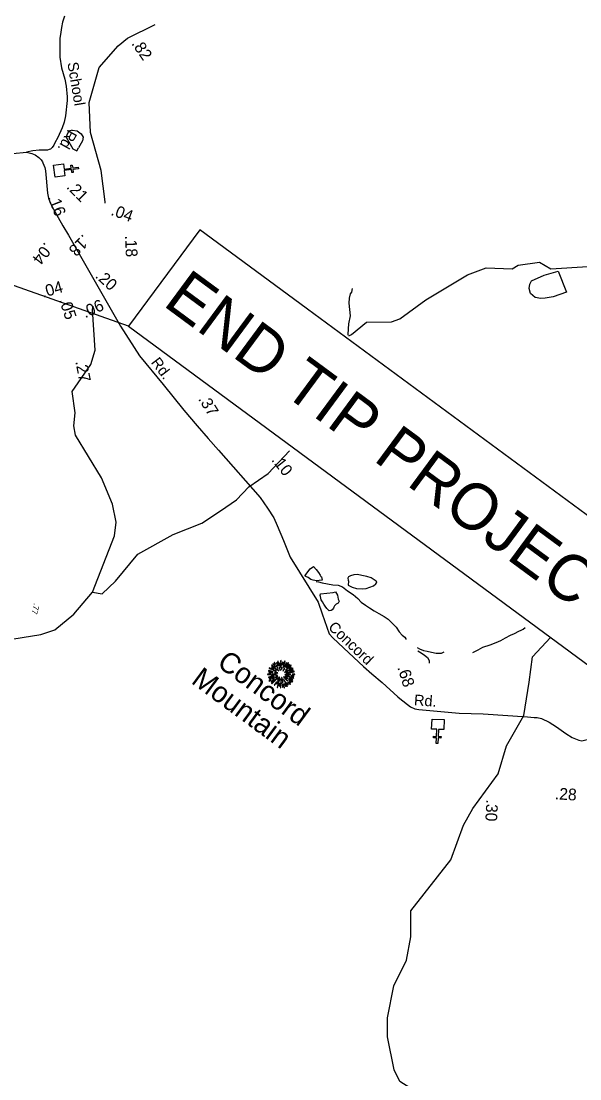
# Model space of a CAD drawing. Extents: x 945666 to 965748, y 644452 to 663300.
# Drawn here: x 954782 to 955557, y 657119 to 658587 of the extents above; entities that cross this region are included whole.
import ezdxf

# ---------------------------------------------------------------- set-up
doc = ezdxf.new("R2010")
doc.units = 0
for name, color, linetype in [('Exist Cultural Church CELL', 7, 'Continuous'), ('Exist Geographical Mountain Summit CELL', 7, 'Continuous'), ('Exist Geographical Mountain Summit Label', 7, 'Continuous'), ('Exist Hydrographic Creek Single Shore', 7, 'Continuous'), ('Exist Hydrographic Misc Water Feature', 7, 'Continuous'), ('Exist Hydrographic Pond Under 1500 Sq Ft', 7, 'Continuous'), ('Exist Road Secondary Mileage Tenths English Label', 7, 'Continuous'), ('Exist Road Secondary Type 51 Attributed', 7, 'Continuous'), ('Exist Road Secondary Type 51 Label', 7, 'Continuous'), ('Old_Level_48', 7, 'Continuous'), ('Prop EOT', 7, 'Continuous'), ('Sheet Title CELL', 7, 'Continuous')]:
    doc.layers.add(name, color=color, linetype=linetype)

msp = doc.modelspace()

# ---------------------------------------------------------------- linework, layer by layer
at = {"layer": 'Exist Cultural Church CELL'}
for points in [[(954840.6, 658388.7), (954841.5, 658381.4), (954851.3, 658382.6), (954850.8, 658386.8), (954852.8, 658387), (954853.4, 658382.9), (954861.1, 658383.9), (954861.4, 658381.8), (954853.6, 658380.8), (954854.1, 658376.7), (954852.1, 658376.5), (954851.6, 658380.6), (954841.8, 658379.3), (954842.7, 658371.9), (954828.9, 658370.2), (954826.8, 658387)], [(955368.1, 657603.7), (955360.7, 657604.1), (955360.2, 657594.2), (955364.3, 657594), (955364.2, 657591.9), (955360.1, 657592.2), (955359.7, 657584.4), (955357.6, 657584.5), (955358, 657592.3), (955353.8, 657592.5), (955354, 657594.5), (955358.1, 657594.3), (955358.6, 657604.2), (955351.1, 657604.6), (955351.8, 657618.4), (955368.8, 657617.6)]]:
    msp.add_lwpolyline(points, close=True, dxfattribs=at)
at = {"layer": 'Exist Geographical Mountain Summit CELL'}
for points in [[(955141.6, 657699.3), (955142.5, 657692.6), (955143, 657692.6), (955142.4, 657699.5)], [(955125, 657685.6), (955125, 657685), (955131.2, 657683.5), (955131.4, 657684.2)], [(955126.1, 657689.3), (955125.9, 657688.6), (955130.5, 657687), (955130.5, 657687.5)], [(955129.1, 657690.4), (955132.3, 657688.2), (955132.6, 657688.6), (955129.4, 657691)], [(955129.2, 657693.1), (955136.2, 657686.9), (955136.5, 657687.1), (955129.6, 657693.7)], [(955131.1, 657695.1), (955134.7, 657691), (955135.1, 657691.2), (955131.6, 657695.5)], [(955131.8, 657686.9), (955131.6, 657686.4), (955135.7, 657684.7), (955135.9, 657685.1)], [(955132.9, 657696.9), (955134.6, 657694.3), (955134.9, 657694.5), (955133.4, 657697.3)], [(955135.6, 657692.2), (955137.9, 657688.6), (955138.2, 657688.7), (955136.1, 657692.4)], [(955136, 657696.4), (955137.4, 657692.7), (955137.9, 657692.8), (955136.6, 657696.6)], [(955137.6, 657698.3), (955139.4, 657692), (955139.8, 657692.1), (955138.3, 657698.5)], [(955137.6, 657686.8), (955139.2, 657685.2), (955139.4, 657685.4), (955138, 657687.2)], [(955139.8, 657689.9), (955141, 657686), (955141.4, 657686.2), (955140.3, 657690.1)], [(955140.3, 657695.8), (955141.5, 657690.2), (955141.9, 657690.3), (955141, 657696.1)], [(955142.9, 657689.8), (955143.1, 657687), (955143.5, 657687.1), (955143.5, 657689.8)], [(955144.6, 657697.3), (955144.6, 657693.8), (955144.9, 657693.8), (955145.3, 657697.4)], [(955147.4, 657698.8), (955145, 657689.7), (955145.4, 657689.6), (955148.2, 657698.6)], [(955147.1, 657688.7), (955145, 657685.5), (955145.3, 657685.4), (955147.6, 657688.4)], [(955147, 657690.7), (955147.3, 657690.6), (955150, 657696.3), (955149.5, 657696.5)], [(955147.4, 657683.5), (955147.6, 657683), (955159.2, 657688.1), (955158.9, 657688.9)], [(955148.8, 657686), (955156.3, 657692.9), (955155.8, 657693.5), (955148.5, 657686.3)], [(955152.2, 657696.8), (955148.6, 657691), (955149, 657690.8), (955152.9, 657696.4)], [(955149.7, 657689.9), (955150.1, 657689.6), (955154.1, 657694.2), (955153.6, 657694.6)], [(955149.7, 657682), (955149.8, 657681.6), (955160.6, 657684), (955160.5, 657684.8)], [(955153.3, 657688.3), (955153.6, 657687.9), (955156.7, 657690), (955156.3, 657690.6)], [(955159.2, 657686.6), (955154.4, 657684.7), (955154.6, 657684.4), (955159.4, 657685.9)], [(955123.4, 657680.9), (955123.4, 657680.3), (955128, 657680.3), (955128, 657680.9)], [(955125.1, 657676.5), (955125.2, 657676), (955133.1, 657677.9), (955133, 657678.3)], [(955125.6, 657682.6), (955130, 657682.1), (955130, 657682.7), (955125.8, 657683.3)], [(955125.6, 657671.7), (955125.9, 657671.1), (955128.9, 657672.8), (955128.8, 657673.3)], [(955131.7, 657676.7), (955126.1, 657674.5), (955126.2, 657674), (955131.9, 657676.2)], [(955128.9, 657669.6), (955133.4, 657673.2), (955133.1, 657673.5), (955128.5, 657670.1)], [(955129.1, 657678.6), (955132.5, 657679), (955132.4, 657679.5), (955128.9, 657679.3)], [(955129.1, 657667.8), (955129.5, 657667.3), (955137.7, 657675.7), (955137.5, 657676)], [(955130.2, 657680.8), (955130.2, 657680.2), (955136, 657680.5), (955136, 657680.9)], [(955130.4, 657674.2), (955130.7, 657673.7), (955138, 657677.7), (955137.8, 657678)], [(955133.6, 657683.3), (955133.5, 657682.7), (955137.6, 657682), (955137.8, 657682.5)], [(955134.9, 657678.8), (955135, 657678.3), (955137.4, 657679.2), (955137.3, 657679.5)], [(955136.7, 657666.8), (955138.4, 657670.4), (955138.1, 657670.6), (955136.2, 657667.1)], [(955139.8, 657676.7), (955137.4, 657672.5), (955137.8, 657672.2), (955140.2, 657676.5)], [(955140.8, 657674.6), (955139.4, 657670.8), (955140, 657670.6), (955141.1, 657674.5)], [(955142.1, 657673.2), (955141.7, 657661.5), (955142.3, 657661.5), (955142.5, 657673.1)], [(955143.2, 657676), (955144.5, 657669.4), (955145.1, 657669.6), (955143.6, 657676.1)], [(955145.7, 657677), (955151.2, 657671), (955151.6, 657671.4), (955146.1, 657677.3)], [(955145.7, 657673.8), (955150.9, 657663.8), (955151.5, 657664.3), (955146, 657674)], [(955147.9, 657680.1), (955147.8, 657679.7), (955155.7, 657679.7), (955155.7, 657680.5)], [(955148.3, 657677.3), (955148.1, 657677), (955151.2, 657674.7), (955151.7, 657675.1)], [(955149.4, 657678.5), (955149.4, 657678.2), (955159.7, 657675.2), (955159.9, 657675.8)], [(955152.8, 657673.8), (955158.5, 657670.1), (955158.9, 657670.6), (955153, 657674.1)], [(955153.4, 657671.4), (955156, 657669.2), (955156.3, 657669.6), (955153.7, 657671.7)], [(955154.2, 657675), (955158.5, 657672.8), (955158.8, 657673.5), (955154.2, 657675.3)], [(955156.2, 657678.1), (955160.2, 657677.5), (955160.3, 657678.2), (955156.2, 657678.4)], [(955157.9, 657680.5), (955157.9, 657680), (955161.6, 657680), (955161.5, 657680.7)], [(955135.9, 657670.1), (955133, 657665.4), (955133.5, 657665.2), (955136.4, 657669.8)], [(955138.8, 657668.7), (955136.8, 657662.2), (955137.4, 657662), (955139.2, 657668.6)], [(955140.4, 657668.5), (955139.8, 657664.2), (955140.4, 657664.1), (955140.9, 657668.4)], [(955143.5, 657668), (955144.4, 657662.6), (955145, 657662.7), (955144, 657668.1)], [(955145.3, 657666.8), (955146.5, 657661.7), (955147.2, 657661.9), (955145.7, 657666.9)], [(955147.1, 657667.2), (955148.7, 657663.9), (955149.3, 657664.1), (955147.7, 657667.5)], [(955150.5, 657668.7), (955152.1, 657666.2), (955152.6, 657666.5), (955150.9, 657668.9)], [(955152.5, 657669.3), (955154.9, 657666.4), (955155.4, 657666.9), (955152.9, 657669.7)]]:
    msp.add_lwpolyline(points, close=True, dxfattribs=at)
at = {"layer": 'Exist Hydrographic Creek Single Shore'}
for points in [[(954898.3, 658334), (954898.4, 658335.9), (954892.8, 658379.4), (954878, 658432.2), (954876.4, 658473.7), (954890.1, 658522.4), (954916.7, 658552.5), (954929.3, 658563.2), (954967.7, 658582)], [(955236.5, 658150), (955240.3, 658152), (955260.7, 658169.1), (955295.4, 658169.3), (955307.2, 658173.7), (955343.4, 658200.2), (955401.2, 658234.8), (955426.9, 658244.6), (955462.8, 658242.8), (955471.2, 658248.2), (955500.7, 658252.3), (955516.6, 658242.8), (955567.8, 658246.4), (955621.9, 658264), (955644.2, 658272.6), (955662.4, 658287.1)], [(954881, 657794.4), (954911.3, 657872.7), (954913.9, 657891.7), (954908.5, 657916.3), (954893.4, 657953.1), (954857.3, 658012.1), (954855.1, 658025), (954856.9, 658043), (954852.7, 658072.6), (954878.5, 658110.3), (954884.7, 658130.3), (954881.1, 658186.8), (954881.9, 658191.2)], [(955058.3, 657907.4), (955080.6, 657922.6), (955097.7, 657940.7), (955124.7, 657959.1), (955154, 657990.5)], [(954881, 657794.4), (954894.4, 657792.1), (954912.6, 657809.9), (954943.6, 657847.3), (954992.8, 657874.5), (955032.7, 657890.1), (955058.3, 657907.4)], [(954720.4, 657112.4), (954738.9, 657151.4), (954750.2, 657247.6), (954746.3, 657261.9), (954711.5, 657308.6), (954704.7, 657355.7), (954697.4, 657378), (954701.8, 657394), (954699, 657409.6), (954705.5, 657421.2), (954706, 657435.9), (954732.3, 657481.3), (954749.4, 657520.3), (954748.5, 657529.6), (954755.3, 657569.5), (954762.6, 657645.1), (954757.2, 657699.2), (954750.3, 657720.1), (954757.3, 657727.2), (954809.4, 657735.5), (954828.6, 657742.2), (954855.2, 657763.7), (954881, 657794.4)], [(955403.4, 657010.4), (955376.7, 657048.1), (955349.4, 657065.9), (955341.2, 657076.5), (955334.8, 657098.1), (955307.2, 657115.6), (955299.4, 657131.8), (955290.1, 657177.7), (955290.2, 657203.9), (955299, 657248.2), (955316.3, 657283.9), (955322.5, 657316.2), (955322.2, 657352.4), (955378.1, 657422.9), (955395.6, 657471.2), (955408.4, 657494.3), (955443.7, 657542.3), (955455.3, 657581.3), (955478.9, 657623.4), (955486.5, 657669.6), (955491, 657704.9), (955516.3, 657731.7)]]:
    msp.add_lwpolyline(points, dxfattribs=at)
at = {"layer": 'Exist Hydrographic Misc Water Feature'}
for points in [[(955240.8, 658215.7), (955239.9, 658210.5), (955238.3, 658208.4), (955236.8, 658202.3), (955236.3, 658195.4), (955238.3, 658177.9), (955235.9, 658166.5), (955235.2, 658152.2), (955235.2, 658150.9)], [(955191.2, 657809.4), (955194.2, 657808.6), (955199.3, 657807.5), (955206.9, 657805.9), (955214.3, 657804.7), (955221.4, 657804.1), (955227.6, 657801.9), (955234.6, 657796.4), (955242.2, 657791.4), (955248.9, 657785.6), (955253.7, 657780.8), (955259.6, 657776.5), (955265.2, 657772.7), (955271.7, 657768.7), (955278.2, 657764.8), (955285.2, 657760.7), (955291.1, 657756.8), (955296.7, 657751.3), (955302.2, 657745.7), (955306, 657739.5), (955310.4, 657734.7), (955313.9, 657731.9), (955315.6, 657729.9), (955315.6, 657728.6)], [(955408.2, 657710.9), (955416, 657714.5), (955422.4, 657718), (955432.2, 657721.6), (955440.7, 657724.5), (955447.4, 657727.5), (955453.7, 657730.9), (955460.7, 657734.7), (955466.3, 657736.9), (955472.2, 657740.2), (955475.6, 657741.9), (955478, 657742.9), (955480.9, 657745.3)], [(955331.3, 657717.6), (955334.4, 657715.9), (955339.8, 657713.6), (955345, 657712.5), (955350.9, 657711.2), (955357.4, 657709.8), (955361.4, 657709.9), (955365.1, 657710), (955368.7, 657711.5)], [(955332.1, 657713), (955336.5, 657710.2), (955341.4, 657707.1), (955345.3, 657704), (955347.3, 657700.8), (955347.9, 657699), (955347.7, 657695.8)]]:
    msp.add_lwpolyline(points, dxfattribs=at)
at = {"layer": 'Exist Hydrographic Pond Under 1500 Sq Ft'}
msp.add_line((955197.7, 657816), (955198.4, 657815.6), dxfattribs=at)
for points in [[(954852.5, 658435.5), (954848, 658434.1), (954845.6, 658429.8), (954844.2, 658425.5), (954853.7, 658409.4), (954859, 658406.9), (954861.3, 658410.7)], [(954852.5, 658435.5), (954859.5, 658434.3), (954865.1, 658430.5), (954867.9, 658425.7), (954867.2, 658420.6), (954861.3, 658410.7)], [(955507.3, 658234), (955526.6, 658239.6), (955538.5, 658210.6), (955520, 658204), (955508.9, 658202.2), (955502.7, 658201.8), (955495, 658203), (955488.4, 658208.9), (955486.5, 658215.7), (955487.3, 658221.7), (955489.7, 658226.4), (955507.3, 658234)], [(955199.2, 657811), (955195.4, 657810.7), (955191.7, 657810.3), (955187.1, 657811.2), (955183.9, 657812.1), (955180, 657814.8), (955176.7, 657816.1), (955175.5, 657817), (955182.7, 657826.6)], [(955182.7, 657826.6), (955187.3, 657830), (955191, 657825.8), (955194.2, 657821.9), (955196.7, 657817.9), (955197.7, 657816)], [(955275.3, 657808.9), (955272.9, 657810.5), (955267.3, 657814.3), (955261.3, 657816.3), (955254.5, 657817.4), (955248.4, 657818.8), (955243.2, 657818.6), (955238.9, 657816.9), (955236.1, 657815.9), (955234.9, 657813.9), (955235.6, 657811), (955235.8, 657809.5)], [(955198.4, 657815.6), (955199, 657813.2), (955199.2, 657811)], [(955235.8, 657809.5), (955235.3, 657804.3), (955241, 657801.4), (955247.2, 657799.6), (955255.2, 657798.9), (955260.5, 657799.7), (955265.7, 657801.3), (955270.5, 657803.2), (955273.9, 657805.8), (955275, 657807.2), (955275.3, 657808.9)], [(955214.8, 657793.8), (955217.8, 657795.1), (955220.5, 657790.1), (955221.7, 657784.8), (955222.9, 657781.8), (955221.4, 657779.4), (955219, 657777.6), (955216.7, 657775.5), (955215.4, 657773.5), (955215, 657772.2), (955213.4, 657770.1), (955211.7, 657768.8), (955209.1, 657768.5), (955206, 657771.6), (955203.6, 657774.8), (955201.7, 657778), (955199.7, 657780.9), (955198, 657783.8), (955196.9, 657788.3), (955196.6, 657789.6), (955196.9, 657792), (955214.8, 657793.8)]]:
    msp.add_lwpolyline(points, dxfattribs=at)
at = {"layer": 'Exist Road Secondary Type 51 Attributed'}
for points in [[(954842.2, 658593.4), (954839.4, 658585.1), (954837.9, 658578), (954836.5, 658568.2), (954835.8, 658563.2), (954835.5, 658550.9), (954835.8, 658536.7), (954837.9, 658521.7), (954842.6, 658506.3), (954844.2, 658496.4), (954845.7, 658481.8), (954845.8, 658476.5), (954843.6, 658455.2), (954841.7, 658446.4), (954838.6, 658438.8), (954832.8, 658425.4), (954828.7, 658417.6), (954827.1, 658414.6), (954824.9, 658411.2), (954822.7, 658409.2), (954820.7, 658408.4), (954818.3, 658407.7), (954806.9, 658407.7), (954798.2, 658406.8), (954789.3, 658404.9)], [(954750.3, 658407.1), (954756.9, 658404.5), (954763.1, 658403.6), (954770.4, 658403.1), (954789.3, 658404.9)], [(954789.3, 658404.9), (954796.9, 658403.1), (954801.3, 658401.1), (954806.4, 658397.4), (954809.5, 658394), (954811.4, 658391.5), (954812, 658389.9), (954814.8, 658383.5), (954815.5, 658378.8), (954818.4, 658348.1), (954819.8, 658341.2), (954821.8, 658335.8), (954824.4, 658329.8), (954839.6, 658302.6), (954847.6, 658289.6)], [(954847.6, 658289.6), (954919.7, 658163.3)], [(954919.7, 658163.3), (954946.1, 658122.4), (954978.7, 658082.6)], [(954978.7, 658082.6), (955007.6, 658046.9), (955026.2, 658025)], [(955026.2, 658025), (955041.5, 658007.7), (955055.8, 657991.4), (955113.5, 657925.9), (955123.6, 657910.9), (955132.3, 657897.7), (955136.8, 657886.7), (955146, 657866), (955154.9, 657843), (955193.7, 657780.7), (955199.6, 657764.2), (955208.9, 657736.8), (955214, 657731.2), (955236.5, 657710.4), (955256.9, 657691.5), (955268.2, 657681.2), (955282.8, 657669.3), (955304.5, 657649.2), (955307.1, 657647.1)], [(955307.1, 657647.1), (955322, 657635.4), (955328.1, 657632.6), (955333.5, 657631.7), (955389.4, 657626.7), (955422.8, 657625.8), (955484.4, 657621.7), (955493.3, 657620.8), (955497.8, 657620.6), (955503.8, 657619.3), (955514.1, 657613.9)], [(955514.1, 657613.9), (955524.5, 657607.4), (955537.4, 657598.3), (955546.3, 657593), (955555.4, 657588.9), (955559.7, 657588.4), (955573.8, 657591.7), (955585.4, 657596.3), (955599.8, 657601.5), (955611.6, 657603.2)]]:
    msp.add_lwpolyline(points, dxfattribs=at)
at = {"layer": 'Prop EOT'}
msp.add_line((954931, 658163.4), (954472.9, 658324.7), dxfattribs=at)
msp.add_lwpolyline([(955925.6, 657636.6), (955029.8, 658297.3), (954931, 658163.4), (955826.8, 657502.7)], close=True, dxfattribs=at)

# ---------------------------------------------------------------- texts
at = {"layer": 'Exist Geographical Mountain Summit Label'}
for s, p in [('Concord', (955052, 657692.9)), ('Mountain', (955016.4, 657669.1))]:
    msp.add_text(s, height=28.58, rotation=323.5908, dxfattribs=at).set_placement(p)
at = {"layer": 'Exist Road Secondary Mileage Tenths English Label'}
for s, height, rotation, p in [('.82', 16.24, 304.5473, (954934.3, 658555.5)), ('.21', 16.24, 314.7725, (954843.8, 658355.7)), ('.16', 16.24, 291.1297, (954818.6, 658342.5)), ('.04', 16.24, 339.6963, (954905.3, 658318.1)), ('.18', 16.24, 224.8821, (954868, 658291.7)), ('.18', 16.24, 272.6731, (954925.9, 658289.1)), ('.04', 16.24, 231.9977, (954814.9, 658280.8)), ('.20', 16.24, 317.6738, (954883.6, 658231.8)), ('.04', 16.24, 16.2152, (954812.4, 658202.7)), ('.05', 16.24, 288.4825, (954834.4, 658199.7)), ('.06', 16.24, 24.2331, (954870.7, 658174.3)), ('.27', 16.24, 281.3172, (954857, 658114.3)), ('.37', 16.24, 302.0658, (955027, 658062.4)), ('.10', 16.24, 308.406, (955128.3, 657977.6)), ('.77', 8.12, 255.7262, (954799.7, 657779.5)), ('.68', 16.24, 287.6775, (955303.5, 657690)), ('.28', 16.24, 356.3396, (955521.8, 657507.2)), ('.30', 16.24, 267.1776, (955427.2, 657507))]:
    msp.add_text(s, height=height, rotation=rotation, dxfattribs=at).set_placement(p)
at = {"layer": 'Exist Road Secondary Type 51 Label'}
for s, rotation, p in [('School', 279.3927, (954846, 658528.7)), ('Rd.', 240.897, (954847.1, 658437.3)), ('Rd.', 307.297, (954961.3, 658113)), ('Concord', 316.4406, (955206.8, 657744.5)), ('Rd.', 355.957, (955326.4, 657637.6))]:
    msp.add_text(s, height=15, rotation=rotation, dxfattribs=at).set_placement(p)
at = {"layer": 'Old_Level_48'}
msp.add_text('END TIP PROJECT U-5834', height=64.231, rotation=323.5908, dxfattribs=at).set_placement((954976.9, 658193.2))
at = {"layer": 'Sheet Title CELL'}
msp.add_text('RIGHT OF WAY PLANS', height=150, rotation=53.5908, dxfattribs=at).set_placement((955097, 656104.3))

doc.saveas('drawing.dxf')
